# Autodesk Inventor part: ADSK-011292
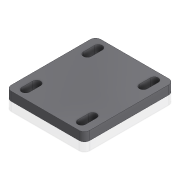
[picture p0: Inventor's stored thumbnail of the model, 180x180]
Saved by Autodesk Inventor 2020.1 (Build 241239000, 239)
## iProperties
Created: 1999-11
Part Number: ADSK-011292
Material: Acier doux
Document SubType Name: Modeling
Designer: sspink
Density: 7.86 g/cm^3
Appearance: Metal-Steel(Polish)
Mass: 652.932 g
Surface Area: 224.54 cm^2
Volume: 83.0703 cm^3
Control State: 0
Checked Out: False
Last Check In By: sspink
Last Check In Date: 1999-12-16
Master: False
Shininess: 0.0
Length Units: 11269
Angle Units: 11279
Time Units: 11290
Mass Units: 11283
Length Display Precision: 3
Angle Display Precision: 2
Compacted: True
Dimensions: 89x10x101,6 mm
Mass: 0,653 kg
DocNumber: ADSK-011292.ipt
Folder: 01 - Themengebiete\Simplification\01 - Packaging machine\
VDS_Category: 3D Komponenten
Density: 0.0
Volumn: 0.0
Area: 0.0
PropertySet Name: Model Information
Author: sspink
Revision Number: -
Title: base plate
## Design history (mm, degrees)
node "Rectangular Pattern1" dims "d12" = 20, "d14" = 70, "d15" = 20, "d17" = 63.5
node "Solide1"
  node "Extrusion1" dims "d2" = 101.6, "d3" = 0
  node "Extrusion2" dims "d10" = 101.6, "d11" = 0
  node "Fillet1" dims "d18" = 6
sketch "Sketch1"
  geometry: L1 (44.5, 5)-(-44.5, 5); L2 (-44.5, 5)-(-44.5, -5); L3 (-44.5, -5)-(44.5, -5); L4 (44.5, -5)-(44.5, 5); 3 further points
  constraints: 8 end point, 2 midpoint, 2 parallel, 1 horizontal, 1 horizontal alignment, 1 perpendicular, 1 vertical alignment
  dimensions: "d0" = 10 distance of L1.end L2.end; "d1" = 89 distance of L2.end L3.end
sketch "Sketch3"
  geometry: L1 (0, 0)-(89, 0) reference; L2 (89, 0)-(89, 101.6) reference; L3 (80.75, 9.55)-(80.75, 22.05); L4 (71.75, 22.05)-(71.75, 9.55); L5 (89, 101.6)-(0, 101.6) reference; L6 (44.5, 0)-(44.5, 101.6); L7 (76.25, 9.55)-(76.25, 22.05); L8 (44.5, 50.8)-(89, 50.8); A1 r 4.5 centre (76.25, 22.05) between (80.75, 22.05) and (71.75, 22.05); A2 r 4.5 centre (76.25, 9.55) between (71.75, 9.55) and (80.75, 9.55); 1 further point
  constraints: 10 end point, 5 midpoint, 4 point on circle, 3 parallel, 3 tangent, 2 centre point, 1 equal radius, 1 vertical
  dimensions: "d6" = 4.5 radius of A1; "d7" = 12.5 distance of L7.start L7.end; "d19" = 31.75 distance between parallel lines of L6 L7; "d20" = 35 distance from line of point (76.25, 15.8) L8
workpoint "Arbeitspunkt1"
workpoint "Arbeitspunkt2"
workpoint "Arbeitspunkt3"
workpoint "Arbeitspunkt4"
workaxis "Arbeitsachse1"
workaxis "Arbeitsachse2"
workaxis "Arbeitsachse3"
workaxis "Arbeitsachse4"
node "Corps solides"
node "Corps surfaciques"
